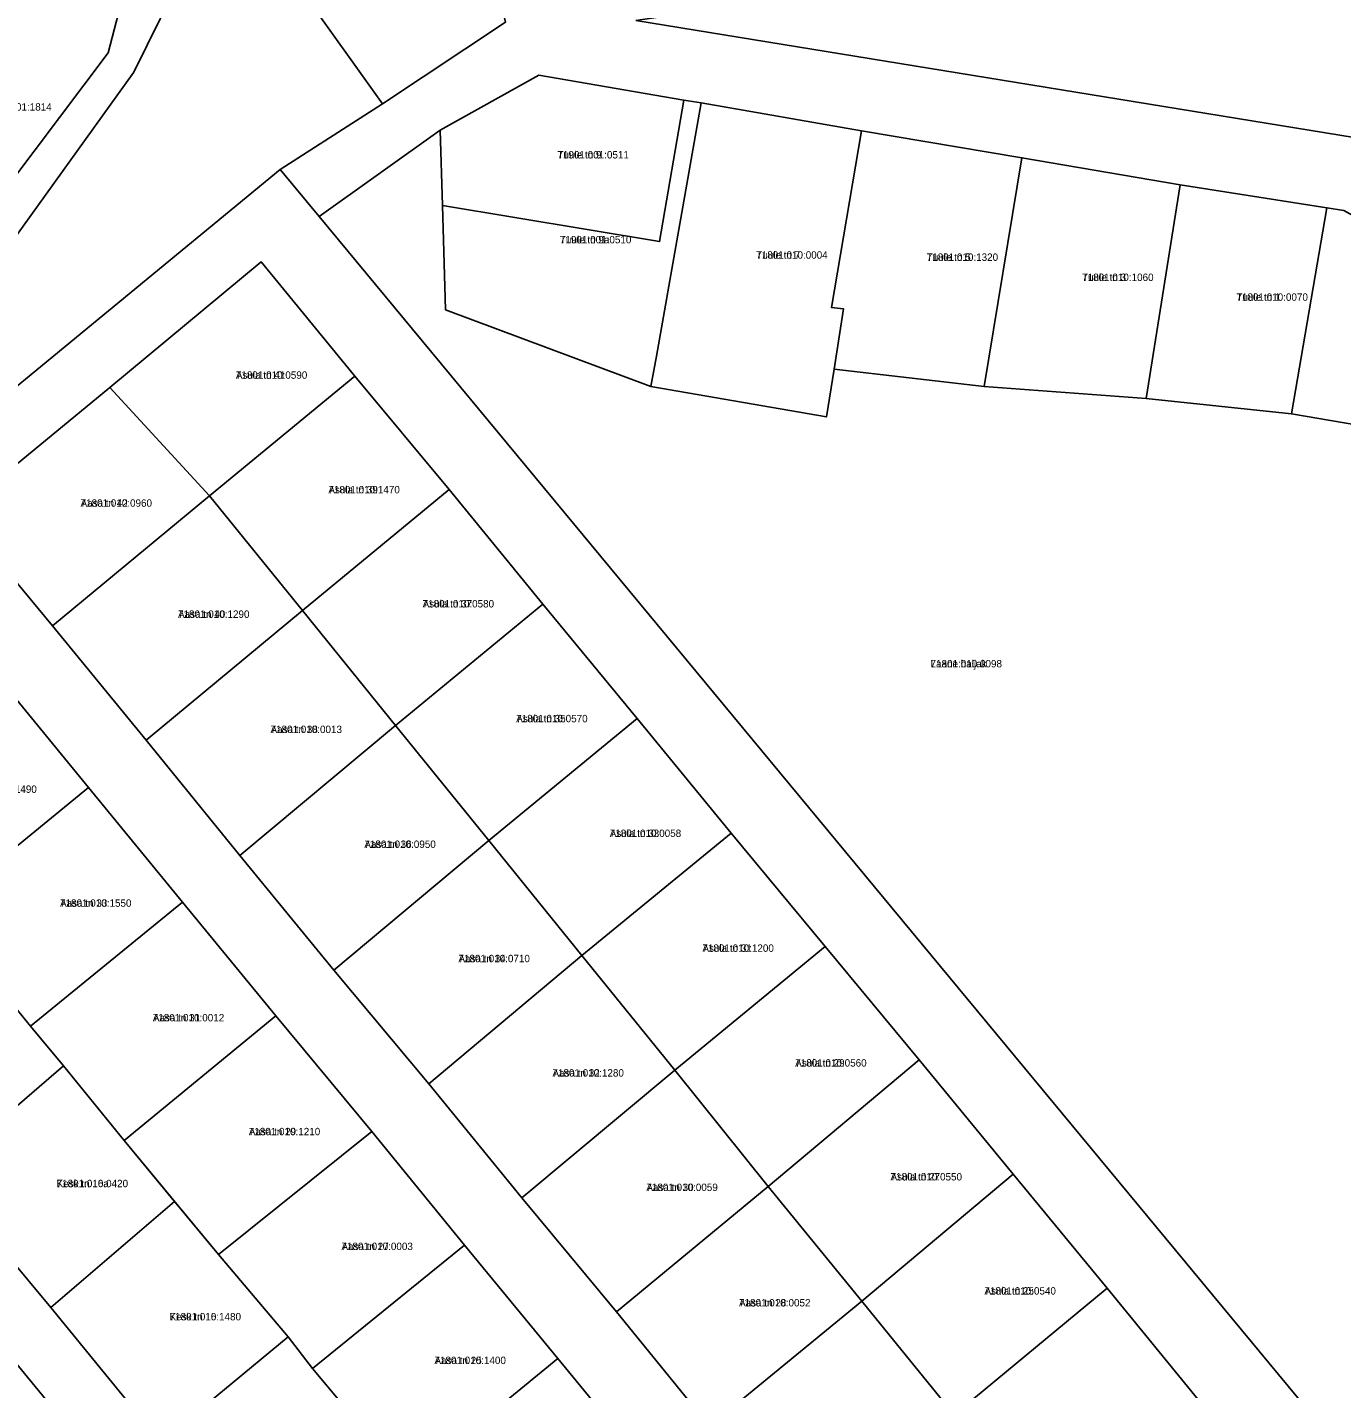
# Model space of a CAD drawing. Extents: x 529768 to 552006, y 6562269 to 6580975.
# Drawn here: x 537467.3 to 537734.1, y 6574194.8 to 6574471 of the extents above; entities that cross this region are included whole.
import ezdxf

# ---------------------------------------------------------------- set-up
doc = ezdxf.new("R2010")
doc.units = 0
for name, color, linetype in [('L_AADRESS', 7, 'Continuous'), ('PIIR', 7, 'Continuous'), ('TUNNUS', 7, 'Continuous')]:
    doc.layers.add(name, color=color, linetype=linetype)

msp = doc.modelspace()

# ---------------------------------------------------------------- linework, layer by layer
at = {"layer": 'PIIR'}
for points in [[(537590.81, 6574472.39), (537630.48, 6574478.33), (537667.63, 6574492.48), (537677.14, 6574495.88), (537719.92, 6574511.97), (537740.27, 6574520.56), (537737.26, 6574539.11), (537730.94, 6574538.1), (537728.4, 6574555.96), (537725.42, 6574575.93), (537746.26, 6574559.07), (537765.85, 6574543.51), (537753.15, 6574444.02), (537739.55, 6574448.19)], [(537522.96, 6574478.54), (537519.08, 6574507.83), (537569.46, 6574516.15), (537574.88, 6574480.1), (537563.26, 6574476.78), (537564.38, 6574472.03), (537539.43, 6574455.47)], [(537440.36, 6574471.77), (537445.63, 6574478.66), (537486.18, 6574475.14), (537483.74, 6574465.85), (537464, 6574439.61), (537456.34, 6574428.53), (537429.38, 6574451.24), (537434.71, 6574460.13), (537432.31, 6574461.86)], [(537551.15, 6574450.16), (537571.18, 6574461.27), (537600.58, 6574456.23), (537595.67, 6574427.54), (537551.61, 6574434.89)], [(537600.58, 6574456.23), (537604.11, 6574455.67), (537595.01, 6574404.33), (537593.89, 6574398.12), (537552.21, 6574413.72), (537551.61, 6574434.89), (537595.67, 6574427.54)], [(537595.01, 6574404.33), (537604.11, 6574455.67), (537636.68, 6574449.98), (537630.55, 6574414.17), (537632.98, 6574413.91), (537631.09, 6574401.67), (537629.53, 6574391.98), (537593.89, 6574398.12)], [(537526.58, 6574432.62), (537551.15, 6574450.16), (537551.61, 6574434.89), (537552.21, 6574413.72), (537593.89, 6574398.12), (537629.53, 6574391.98), (537631.09, 6574401.67), (537661.54, 6574398.13), (537694.42, 6574395.69), (537723.93, 6574392.62), (537753.19, 6574387.57), (537755.56, 6574321.63), (537748.47, 6574284.05), (537751.59, 6574256.19), (537774.75, 6574140.06), (537770.95, 6574137.8)], [(537661.54, 6574398.13), (537631.09, 6574401.67), (537632.98, 6574413.91), (537630.55, 6574414.17), (537636.68, 6574449.98), (537669.21, 6574444.54)], [(537669.21, 6574444.54), (537701.32, 6574439.06), (537694.42, 6574395.69), (537661.54, 6574398.13)], [(537694.42, 6574395.69), (537701.32, 6574439.06), (537731.1, 6574434.41), (537723.93, 6574392.62)], [(537734.55, 6574433.82), (537753.01, 6574423.65), (537753.19, 6574387.57), (537723.93, 6574392.62), (537731.1, 6574434.41)], [(537504.31, 6574375.98), (537484.09, 6574397.95), (537514.81, 6574423.43), (537533.81, 6574400.27)], [(537523.2, 6574352.67), (537504.31, 6574375.98), (537533.81, 6574400.27), (537552.95, 6574377.28)], [(537472.43, 6574349.56), (537453.32, 6574372.65), (537484.09, 6574397.95), (537504.31, 6574375.98)], [(537491.43, 6574326.43), (537472.43, 6574349.56), (537504.31, 6574375.98), (537523.2, 6574352.67)], [(537542.09, 6574329.36), (537523.2, 6574352.67), (537552.95, 6574377.28), (537572, 6574354.01)], [(537560.98, 6574306.05), (537542.09, 6574329.36), (537572, 6574354.01), (537591.13, 6574330.78)], [(537510.45, 6574303.01), (537491.43, 6574326.43), (537523.2, 6574352.67), (537542.09, 6574329.36)], [(537460.81, 6574339.88), (537479.78, 6574316.79), (537448.9, 6574291.54), (537429.96, 6574314.82)], [(537529.53, 6574279.73), (537510.45, 6574303.01), (537542.09, 6574329.36), (537560.98, 6574306.05)], [(537579.87, 6574282.74), (537560.98, 6574306.05), (537591.13, 6574330.78), (537610.16, 6574307.5)], [(537498.84, 6574293.5), (537468.01, 6574268.41), (537452.11, 6574287.88), (537448.9, 6574291.54), (537479.78, 6574316.79)], [(537548.85, 6574256.65), (537529.53, 6574279.73), (537560.98, 6574306.05), (537579.87, 6574282.74)], [(537598.76, 6574259.43), (537579.87, 6574282.74), (537610.16, 6574307.5), (537629.26, 6574284.54)], [(537517.79, 6574270.46), (537487.02, 6574245.19), (537474.68, 6574260.34), (537468.01, 6574268.41), (537498.84, 6574293.5)], [(537452.11, 6574287.88), (537468.01, 6574268.41), (537474.68, 6574260.34), (537449.34, 6574238.56), (537427.02, 6574266.11)], [(537617.67, 6574235.82), (537598.76, 6574259.43), (537629.26, 6574284.54), (537648.32, 6574261.53)], [(537567.7, 6574233.55), (537548.85, 6574256.65), (537579.87, 6574282.74), (537598.76, 6574259.43)], [(537487.02, 6574245.19), (537517.79, 6574270.46), (537537.24, 6574247.03), (537506.11, 6574222.04)], [(537449.34, 6574238.56), (537474.68, 6574260.34), (537487.02, 6574245.19), (537497.22, 6574232.79), (537472.12, 6574211.28)], [(537586.91, 6574210.44), (537567.7, 6574233.55), (537598.76, 6574259.43), (537617.67, 6574235.82)], [(537636.71, 6574212.62), (537617.67, 6574235.82), (537648.32, 6574261.53), (537667.45, 6574238.35)], [(537537.24, 6574247.03), (537556.1, 6574223.92), (537525.19, 6574198.9), (537520.3, 6574205.36), (537506.11, 6574222.04)], [(537655.43, 6574189.5), (537636.71, 6574212.62), (537667.45, 6574238.35), (537686.51, 6574215.21)], [(537605.79, 6574187.21), (537586.91, 6574210.44), (537617.67, 6574235.82), (537636.71, 6574212.62)], [(537497.22, 6574232.79), (537506.11, 6574222.04), (537520.3, 6574205.36), (537494.41, 6574183.98), (537472.12, 6574211.28)], [(537525.19, 6574198.9), (537556.1, 6574223.92), (537574.98, 6574200.96), (537544.26, 6574175.73), (537542.86, 6574177.83)], [(537705.51, 6574191.94), (537674.58, 6574166.4), (537655.43, 6574189.5), (537686.51, 6574215.21)], [(537624.81, 6574164.08), (537605.79, 6574187.21), (537636.71, 6574212.62), (537655.43, 6574189.5)], [(537494.41, 6574183.98), (537520.3, 6574205.36), (537525.19, 6574198.9), (537542.86, 6574177.83), (537517.33, 6574156.62)], [(537485.04, 6574175.65), (537459.79, 6574155.4), (537437.45, 6574182.2), (537462.46, 6574203.17)], [(537594.3, 6574177.5), (537563.4, 6574152.63), (537544.26, 6574175.73), (537574.98, 6574200.96)]]:
    msp.add_lwpolyline(points, close=True, dxfattribs=at)
for points in [[(537522.96, 6574478.54), (537539.43, 6574455.47), (537518.67, 6574442.15), (537448.89, 6574384.8), (537385.19, 6574297.04), (537391.74, 6574289.06), (537367.48, 6574266.71), (537346.58, 6574240.23), (537338.05, 6574252.13), (537488.95, 6574461.89), (537497.08, 6574478.43)], [(537497.08, 6574478.43), (537488.95, 6574461.89), (537338.05, 6574252.13)], [(537464, 6574439.61), (537483.74, 6574465.85), (537486.18, 6574475.14)], [(537734.55, 6574433.82), (537731.1, 6574434.41), (537701.32, 6574439.06), (537669.21, 6574444.54), (537636.68, 6574449.98), (537604.11, 6574455.67), (537600.58, 6574456.23), (537571.18, 6574461.27), (537551.15, 6574450.16), (537526.58, 6574432.62), (537518.67, 6574442.15), (537539.43, 6574455.47), (537564.38, 6574472.03)], [(537590.81, 6574472.39), (537739.55, 6574448.19)], [(537485.04, 6574175.65), (537462.46, 6574203.17), (537439.95, 6574230.65), (537417.3, 6574258.22), (537391.74, 6574289.06), (537385.19, 6574297.04), (537448.89, 6574384.8), (537518.67, 6574442.15), (537526.58, 6574432.62), (537770.95, 6574137.8)], [(537705.51, 6574191.94), (537686.51, 6574215.21), (537667.45, 6574238.35), (537648.32, 6574261.53), (537629.26, 6574284.54), (537610.16, 6574307.5), (537591.13, 6574330.78), (537572, 6574354.01), (537552.95, 6574377.28), (537533.81, 6574400.27), (537514.81, 6574423.43), (537484.09, 6574397.95), (537453.32, 6574372.65), (537472.43, 6574349.56), (537491.43, 6574326.43), (537510.45, 6574303.01), (537529.53, 6574279.73), (537548.85, 6574256.65), (537567.7, 6574233.55), (537586.91, 6574210.44), (537605.79, 6574187.21)], [(537594.3, 6574177.5), (537574.98, 6574200.96), (537556.1, 6574223.92), (537537.24, 6574247.03), (537517.79, 6574270.46), (537498.84, 6574293.5), (537479.78, 6574316.79), (537460.81, 6574339.88), (537443.38, 6574361.2), (537418.11, 6574329.45), (537418.41, 6574329.02), (537398.66, 6574302.87), (537399.29, 6574299.79), (537427.02, 6574266.11), (537449.34, 6574238.56), (537472.12, 6574211.28), (537494.41, 6574183.98)]]:
    msp.add_lwpolyline(points, dxfattribs=at)

# ---------------------------------------------------------------- texts
at = {"layer": 'L_AADRESS'}
for s, p in [('Tuule tn 9', (537574.94, 6574444.4)), ('Tuule tn 9a', (537575.44, 6574427.18)), ('Tuule tn 7', (537615.29, 6574424.08)), ('Tuule tn 5', (537649.88, 6574423.63)), ('Tuule tn 3', (537681.43, 6574419.55)), ('Tuule tn 1', (537712.76, 6574415.53)), ('Asula tn 41', (537509.66, 6574399.71)), ('Asula tn 39', (537528.44, 6574376.47)), ('Aasa tn 42', (537478.14, 6574373.75)), ('Asula tn 37', (537547.57, 6574353.32)), ('Aasa tn 40', (537497.92, 6574351.21)), ('Laane haljak', (537650.66, 6574341.16)), ('Asula tn 35', (537566.56, 6574330.03)), ('Aasa tn 38', (537516.7, 6574327.84)), ('Aasa tn 36', (537535.74, 6574304.54)), ('Asula tn 33', (537585.55, 6574306.76)), ('Aasa tn 33', (537473.97, 6574292.6)), ('Asula tn 31', (537604.36, 6574283.46)), ('Aasa tn 34', (537554.84, 6574281.35)), ('Aasa tn 31', (537492.8, 6574269.35)), ('Aasa tn 32', (537573.92, 6574258.15)), ('Asula tn 29', (537623.19, 6574260.18)), ('Aasa tn 29', (537512.29, 6574246.25)), ('Kesk tn 16a', (537473.28, 6574235.71)), ('Asula tn 27', (537642.55, 6574237.08)), ('Aasa tn 30', (537592.98, 6574234.94)), ('Aasa tn 27', (537531.09, 6574222.96)), ('Asula tn 25', (537661.61, 6574213.93)), ('Aasa tn 28', (537611.79, 6574211.52)), ('Kesk tn 16', (537496.21, 6574208.7)), ('Aasa tn 25', (537549.97, 6574199.83))]:
    msp.add_text(s, height=1.5, dxfattribs=at).set_placement(p)
at = {"layer": 'TUNNUS'}
for s, p in [('71801:001:1814', (537457.78, 6574454.11)), ('71901:001:0511', (537574.94, 6574444.4)), ('71901:001:0510', (537575.44, 6574427.18)), ('71801:010:0004', (537615.29, 6574424.08)), ('71801:010:1320', (537649.88, 6574423.63)), ('71801:010:1060', (537681.43, 6574419.55)), ('71801:010:0070', (537712.76, 6574415.53)), ('71801:010:0590', (537509.66, 6574399.71)), ('71801:010:1470', (537528.44, 6574376.47)), ('71801:010:0960', (537478.14, 6574373.75)), ('71801:010:0580', (537547.57, 6574353.32)), ('71801:010:1290', (537497.92, 6574351.21)), ('71801:010:0098', (537650.66, 6574341.16)), ('71801:010:0570', (537566.56, 6574330.03)), ('71801:010:0013', (537516.7, 6574327.84)), ('71801:010:1490', (537454.76, 6574315.71)), ('71801:010:0950', (537535.74, 6574304.54)), ('71801:010:0058', (537585.55, 6574306.76)), ('71801:010:1550', (537473.97, 6574292.6)), ('71801:010:1200', (537604.36, 6574283.46)), ('71801:010:0710', (537554.84, 6574281.35)), ('71801:010:0012', (537492.8, 6574269.35)), ('71801:010:1280', (537573.92, 6574258.15)), ('71801:010:0560', (537623.19, 6574260.18)), ('71801:010:1210', (537512.29, 6574246.25)), ('71801:010:0420', (537473.28, 6574235.71)), ('71801:010:0550', (537642.55, 6574237.08)), ('71801:010:0059', (537592.98, 6574234.94)), ('71801:010:0003', (537531.09, 6574222.96)), ('71801:010:0540', (537661.61, 6574213.93)), ('71801:010:0052', (537611.79, 6574211.52)), ('71801:010:1480', (537496.21, 6574208.7)), ('71801:010:1400', (537549.97, 6574199.83))]:
    msp.add_text(s, height=1.5, dxfattribs=at).set_placement(p)

doc.saveas('drawing.dxf')
